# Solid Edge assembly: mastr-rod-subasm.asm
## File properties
Author: Vicky Raina
Template: Normal.asm
Last saved by: CADCIM
Revision: 14
Application: Solid Edge
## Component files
master rod.par
piston.par
piston pin.par
piston pin plug.par
piston ring.par
master rod bearing.par
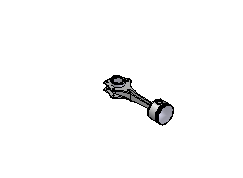
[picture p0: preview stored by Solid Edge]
